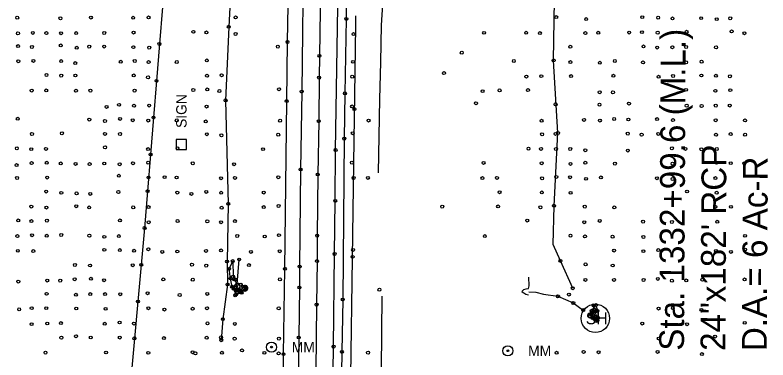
# Model space of a CAD drawing. Extents: x 20503438 to 20508873, y 7964251 to 7984667.
# Drawn here: x 20506371 to 20506880, y 7966054 to 7966287 of the extents above; entities that cross this region are included whole.
import ezdxf

# ---------------------------------------------------------------- set-up
doc = ezdxf.new("R2010")
doc.units = 0
for name, color, linetype in [('SurBreakLine', 7, 'Continuous'), ('SurDrainageArrowDown', 7, 'Continuous'), ('SurDrainageArrowUp', 7, 'Continuous'), ('SurEdgeRoadPaved', 7, 'Continuous'), ('SurEdgeShoulderPaved', 7, 'Continuous'), ('SurGuardRailCable', 7, 'Continuous'), ('SurNaturalCells', 7, 'Continuous'), ('SurPointsNonDTM', 7, 'Continuous'), ('SurRoadPoints', 7, 'Continuous'), ('SurSurveyPoints', 7, 'Continuous'), ('SurTxtDrainage', 7, 'Continuous')]:
    doc.layers.add(name, color=color, linetype=linetype)

msp = doc.modelspace()

# ---------------------------------------------------------------- linework, layer by layer
at = {"layer": 'SurBreakLine'}
for points in [[(20506582.81, 7966724.92), (20506582.26, 7966677.31), (20506582.09, 7966663.27), (20506581.59, 7966615.11), (20506580.38, 7966502.13), (20506579.87, 7966469.3), (20506579.47, 7966429.21), (20506579.05, 7966404.24), (20506578.73, 7966381.34), (20506578.04, 7966321.61), (20506576.98, 7966259.67), (20506576.78, 7966244.96), (20506576.56, 7966215.41), (20506575.87, 7966179.43), (20506575.47, 7966138), (20506575.36, 7966120.77), (20506575.03, 7966091.32), (20506574.47, 7966046.48)], [(20506524.33, 7966099.4), (20506520.71, 7966098.29), (20506517.91, 7966103.33), (20506516.85, 7966109.08), (20506515.87, 7966115.5), (20506518.34, 7966120.79), (20506518.54, 7966110.27), (20506519.05, 7966108.49), (20506521.38, 7966105.16)], [(20506521.38, 7966105.16), (20506522.69, 7966121.79)], [(20506718.49, 7966097.81), (20506716.49, 7966098.25), (20506715.19, 7966099.04), (20506714.23, 7966099.69), (20506714.38, 7966100.67), (20506715.33, 7966101.57), (20506716.74, 7966102.04), (20506718.43, 7966102.3), (20506718.95, 7966104.15), (20506718.63, 7966109.88)]]:
    msp.add_lwpolyline(points, dxfattribs=at)
for points in [[(20506523.75, 7966102.32), (20506523.75, 7966099.6), (20506521.29, 7966099.88), (20506519.07, 7966102.09), (20506518.23, 7966103.41), (20506520.53, 7966104.04), (20506521.78, 7966101.72)], [(20506764.96, 7966080.6), (20506763.97, 7966080.14), (20506761.46, 7966082.36), (20506760.29, 7966084.46), (20506761.04, 7966087.19), (20506762.83, 7966088.28), (20506762.39, 7966090.86), (20506764.05, 7966090.99), (20506765.05, 7966087.15), (20506765.42, 7966082.37)], [(20506763.1, 7966081.62), (20506762.52, 7966082.44), (20506761.57, 7966084.28), (20506762.93, 7966086.64), (20506763.82, 7966086.68), (20506763.93, 7966083.3), (20506764.35, 7966081.47)]]:
    msp.add_lwpolyline(points, close=True, dxfattribs=at)
at = {"layer": 'SurDrainageArrowDown'}
for points in [[(20506616.88, 7966180.41), (20506617.4, 7966205.4), (20506617.92, 7966230.4), (20506618.45, 7966255.39), (20506618.97, 7966280.39), (20506620.54, 7966305.33), (20506622.35, 7966330.27), (20506622.07, 7966354.47), (20506621.79, 7966378.67), (20506621.52, 7966402.88), (20506621.24, 7966427.08), (20506620.96, 7966451.29), (20506620.68, 7966475.49), (20506621.28, 7966497.96), (20506622.23, 7966519.72), (20506623.18, 7966541.47), (20506623.65, 7966564.87), (20506623.65, 7966589.87), (20506623.79, 7966614.5), (20506624.24, 7966638.28), (20506624.7, 7966662.06), (20506625.16, 7966685.84), (20506625.61, 7966709.62), (20506625.94, 7966733.94)], [(20506523.75, 7966721.59), (20506524.08, 7966654.91), (20506523.46, 7966584.86), (20506526.32, 7966516.32), (20506520.79, 7966470.76), (20506521.88, 7966436.58), (20506518.64, 7966398.81), (20506514.26, 7966328.87), (20506517.2, 7966310.23), (20506515.68, 7966279.39), (20506513.5, 7966229.59), (20506515.33, 7966159.59), (20506514.55, 7966120.49), (20506514.84, 7966104.97), (20506511.67, 7966081.49), (20506510.59, 7966067.23)], [(20506470.8, 7966292.66), (20506468.79, 7966267.75), (20506466.78, 7966242.83), (20506464.76, 7966217.91), (20506462.75, 7966192.99), (20506460.74, 7966168.07), (20506458.72, 7966143.16), (20506456.48, 7966118.26), (20506454.18, 7966093.37), (20506451.89, 7966068.48), (20506449.59, 7966043.59)], [(20506619.2, 7966097.06), (20506618.97, 7966072.88), (20506618.74, 7966047.06), (20506618.49, 7966020.9), (20506618.27, 7965997.06), (20506618.04, 7965972.06), (20506617.81, 7965947.06), (20506617.58, 7965922.17), (20506617.16, 7965898.81), (20506616.37, 7965877.03), (20506615.69, 7965858.08), (20506614.95, 7965837.72), (20506614.27, 7965818.75), (20506613.48, 7965796.99), (20506612.75, 7965776.62), (20506612.14, 7965759.68)]]:
    msp.add_lwpolyline(points, dxfattribs=at)
at = {"layer": 'SurDrainageArrowUp'}
for points in [[(20506748.37, 7966102.43), (20506739.98, 7966120.94), (20506735.03, 7966132), (20506735.65, 7966158.21), (20506738.35, 7966207.5), (20506735.41, 7966256.62), (20506736, 7966297.52), (20506735.47, 7966344.97), (20506731.78, 7966371.15), (20506731.51, 7966393.42), (20506729.75, 7966442.32), (20506728.92, 7966490.67), (20506727.65, 7966541.52), (20506726.65, 7966586.02), (20506725.58, 7966633.07), (20506725.56, 7966682.41), (20506728.02, 7966733.71)], [(20506718.57, 7966099.98), (20506723.31, 7966099.83), (20506728.62, 7966098.37), (20506738.34, 7966096.95), (20506748.71, 7966092.43), (20506755.43, 7966087.63)]]:
    msp.add_lwpolyline(points, dxfattribs=at)
at = {"layer": 'SurEdgeRoadPaved'}
for points in [[(20506571.13, 7966726.82), (20506570.83, 7966695.86), (20506570.09, 7966639.42), (20506569.8, 7966614.3), (20506569.59, 7966591.6), (20506568.51, 7966495.95), (20506567.62, 7966430.5), (20506567.22, 7966396.52), (20506566.49, 7966355.87), (20506566.21, 7966336.33), (20506565, 7966235.53), (20506564.23, 7966182.81), (20506563.62, 7966117.05), (20506563.45, 7966102.98), (20506562.98, 7966069.12), (20506561.69, 7965956.65)], [(20506586.39, 7966046.04), (20506586.58, 7966062.88), (20506587.24, 7966125.61), (20506587.67, 7966161.5), (20506587.93, 7966195.96), (20506590.01, 7966334.68), (20506590.5, 7966371.48), (20506591.96, 7966478.18), (20506591.99, 7966480.99), (20506592.1, 7966489.42), (20506593.34, 7966593.17), (20506593.52, 7966612.66), (20506594.1, 7966668.59), (20506594.21, 7966677.21), (20506594.79, 7966724.61)]]:
    msp.add_lwpolyline(points, dxfattribs=at)
at = {"layer": 'SurEdgeShoulderPaved'}
for points in [[(20506552.57, 7966028.45), (20506552.68, 7966057.72), (20506553.65, 7966115.57), (20506554.86, 7966229.07), (20506555.39, 7966269.1), (20506555.74, 7966293.81), (20506557.36, 7966406.54), (20506557.74, 7966443.63), (20506558.13, 7966478.73), (20506558.55, 7966512.75), (20506558.65, 7966520.93), (20506559.14, 7966552.93), (20506559.31, 7966580.85), (20506559.62, 7966608.8), (20506561.22, 7966731.44)], [(20506600.27, 7966712.13), (20506599.16, 7966608.62), (20506599.01, 7966594.45), (20506598.05, 7966493.9), (20506597.53, 7966458.7), (20506596.92, 7966422.46), (20506595.16, 7966284.71), (20506594.2, 7966234.33), (20506593.75, 7966203.67), (20506592.8, 7966094.73), (20506592.19, 7966059.31), (20506591.79, 7966030.9)]]:
    msp.add_lwpolyline(points, dxfattribs=at)
at = {"layer": 'SurGuardRailCable'}
msp.add_lwpolyline([(20506596.16, 7965301.88), (20506594.34, 7965701.8), (20506594.71, 7965733.27), (20506595.45, 7965806.52), (20506596.03, 7965869.84), (20506597.23, 7965978.92), (20506600.18, 7966186.78), (20506601.51, 7966279.91), (20506601.63, 7966286.68)], dxfattribs=at)
at = {"layer": 'SurNaturalCells'}
msp.add_circle((20506763.65, 7966082.03), 9.59, dxfattribs=at)
at = {"layer": 'SurPointsNonDTM'}
for centre in [(20506600.69, 7966223.66), (20506599.46, 7966123.68), (20506617.55, 7966101.43)]:
    msp.add_circle(centre, 1, dxfattribs=at)
at = {"layer": 'SurRoadPoints'}
msp.add_lwpolyline([(20506487.04, 7966199.68), (20506487.04, 7966199.68), (20506487.04, 7966203.11), (20506480.18, 7966203.11), (20506480.18, 7966196.25), (20506487.04, 7966196.25), (20506487.04, 7966199.68)], dxfattribs=at)
for centre, radius in [((20506544.57, 7966062.54), 3.43), ((20506544.57, 7966062.54), 0.571), ((20506704.46, 7966060.09), 3.43), ((20506704.46, 7966060.09), 0.571)]:
    msp.add_circle(centre, radius, dxfattribs=at)
at = {"layer": 'SurSurveyPoints'}
for centre in [(20506372.58, 7966285.52), (20506401.8, 7966285.12), (20506422.43, 7966285.59), (20506451.02, 7966285.46), (20506461.43, 7966285.73), (20506520.33, 7966285.69), (20506595.16, 7966284.71), (20506737.14, 7966285.93), (20506757.4, 7966284.59), (20506795.33, 7966285.87), (20506806.12, 7966285.52), (20506815.81, 7966285.03), (20506835.2, 7966285.21), (20506845.74, 7966284.54), (20506854.84, 7966285.1), (20506515.68, 7966279.39), (20506373.11, 7966274.94), (20506383.13, 7966275.23), (20506392.28, 7966275.11), (20506402.23, 7966275.01), (20506412.44, 7966275.12), (20506431.42, 7966275.19), (20506451.25, 7966275.44), (20506491.71, 7966275.96), (20506500.53, 7966275.54), (20506520.28, 7966274.5), (20506600.03, 7966274.44), (20506688.38, 7966275.28), (20506716.83, 7966275.36), (20506726.1, 7966275.09), (20506756.87, 7966275.11), (20506765.57, 7966275.31), (20506786.5, 7966275.48), (20506795.11, 7966275.73), (20506805.79, 7966275.38), (20506825.35, 7966276.01), (20506855.8, 7966276.25), (20506864.46, 7966275), (20506373.19, 7966266.32), (20506402.05, 7966266.78), (20506468.79, 7966267.75), (20506555.39, 7966269.1), (20506382.49, 7966265.71), (20506412.84, 7966265.2), (20506421.31, 7966265.94), (20506431.4, 7966265.95), (20506451.12, 7966265.59), (20506461.87, 7966265.24), (20506548.86, 7966265.92), (20506673.27, 7966261.84), (20506746.68, 7966265.86), (20506796.2, 7966266.08), (20506805.44, 7966265.32), (20506815.71, 7966265.5), (20506825.02, 7966265.72), (20506845.25, 7966265.45), (20506383.52, 7966256.28), (20506402.3, 7966256.13), (20506452.11, 7966256.24), (20506500.83, 7966256.58), (20506576.98, 7966259.67), (20506708.48, 7966256.19), (20506735.41, 7966256.62), (20506776.79, 7966256.2), (20506373.33, 7966256.02), (20506411.8, 7966254.81), (20506442.6, 7966255.69), (20506461.48, 7966255.5), (20506480.48, 7966255.51), (20506599.75, 7966255.64), (20506746.73, 7966255.49), (20506766.65, 7966255), (20506795.86, 7966255.25), (20506825.02, 7966255.32), (20506835.49, 7966255.74), (20506392.4, 7966246.75), (20506402.36, 7966246.31), (20506411.93, 7966246.41), (20506451.41, 7966246.45), (20506500.97, 7966246.25), (20506510.84, 7966246.61), (20506661.23, 7966248.03), (20506727.08, 7966245.95), (20506747.2, 7966246.02), (20506775.83, 7966246.22), (20506816.2, 7966246.09), (20506835.32, 7966246.4), (20506845.19, 7966246.21), (20506461.07, 7966245.14), (20506466.78, 7966242.83), (20506576.78, 7966244.96), (20506599.2, 7966245.6), (20506716.95, 7966245.65), (20506806.37, 7966245.57), (20506854.6, 7966245.84), (20506382.38, 7966236.22), (20506392.19, 7966236.32), (20506412.34, 7966236.08), (20506422.08, 7966236.15), (20506451.94, 7966236.14), (20506491.68, 7966236.61), (20506501.09, 7966236.99), (20506509.38, 7966235.9), (20506549.67, 7966237.07), (20506687.31, 7966235.81), (20506698.81, 7966236.36), (20506718.05, 7966236.52), (20506825.03, 7966236.71), (20506844.8, 7966236.02), (20506854.89, 7966236.47), (20506565, 7966235.53), (20506594.2, 7966234.33), (20506766.56, 7966235.1), (20506775.53, 7966234.99), (20506441.44, 7966226.56), (20506451.58, 7966225.94), (20506461.84, 7966226.07), (20506513.5, 7966229.59), (20506554.86, 7966229.07), (20506682.89, 7966227.64), (20506736.68, 7966226.86), (20506766.43, 7966226.65), (20506786.37, 7966227.42), (20506825.4, 7966225.98), (20506835.52, 7966225.73), (20506845.04, 7966226.01), (20506854.55, 7966226.03), (20506433.05, 7966225.15), (20506500.64, 7966225.38), (20506599.1, 7966225.47), (20506372.94, 7966217.09), (20506421.35, 7966216.57), (20506431.94, 7966215.61), (20506442.16, 7966217.02), (20506450.7, 7966216.14), (20506461.22, 7966215.91), (20506464.76, 7966217.91), (20506480.52, 7966216.05), (20506550.36, 7966215.8), (20506576.56, 7966215.41), (20506610.24, 7966215.92), (20506727.24, 7966215.77), (20506755.97, 7966216.37), (20506766.73, 7966215.9), (20506776.35, 7966216.93), (20506786.01, 7966216.63), (20506805.35, 7966216.91), (20506816.12, 7966216.23), (20506845, 7966216.11), (20506864.86, 7966216.01), (20506500.14, 7966215.31), (20506382.55, 7966206.81), (20506402.81, 7966207.26), (20506431.93, 7966206.85), (20506442.13, 7966206.83), (20506500.84, 7966206.64), (20506510.69, 7966205.92), (20506549.12, 7966206.33), (20506599.56, 7966207.35), (20506727.59, 7966206.6), (20506736.65, 7966206.89), (20506738.35, 7966207.5), (20506785.55, 7966207.06), (20506794.93, 7966206.37), (20506806.2, 7966206.9), (20506845.23, 7966206.26), (20506855.15, 7966206.72), (20506864.93, 7966206.34), (20506593.75, 7966203.67), (20506372.33, 7966197.12), (20506382.04, 7966196.54), (20506392.02, 7966196.7), (20506431.97, 7966197.8), (20506461.1, 7966196.58), (20506480.99, 7966197.16), (20506538.88, 7966196.53), (20506587.93, 7966195.96), (20506718.4, 7966196.87), (20506726.87, 7966196.7), (20506737.02, 7966196.67), (20506746.66, 7966196.66), (20506756.83, 7966195.8), (20506785.58, 7966195.6), (20506815.4, 7966197.11), (20506824.52, 7966196.74), (20506835.36, 7966196.44), (20506845.8, 7966196.63), (20506462.75, 7966192.99), (20506372.12, 7966185.73), (20506382.34, 7966187.08), (20506392.59, 7966187.31), (20506402.02, 7966186.9), (20506412.05, 7966186.56), (20506421.56, 7966186.44), (20506431.43, 7966186.84), (20506441.88, 7966186.33), (20506450.89, 7966186.99), (20506461.16, 7966187.39), (20506491.31, 7966186.97), (20506519.3, 7966186.36), (20506598.95, 7966187.41), (20506688.03, 7966187.22), (20506727.31, 7966187.02), (20506746.8, 7966186.56), (20506756.83, 7966187.33), (20506776.86, 7966186.75), (20506815.83, 7966186.72), (20506845.66, 7966187.43), (20506855.2, 7966187.06), (20506864.4, 7966187), (20506564.23, 7966182.81), (20506372.53, 7966177.04), (20506392.85, 7966177.3), (20506441.31, 7966178.51), (20506461.39, 7966177.3), (20506472.22, 7966177.59), (20506480.39, 7966177.36), (20506510.51, 7966176.87), (20506519.87, 7966177.08), (20506549.18, 7966177.52), (20506575.87, 7966179.43), (20506600.09, 7966177.03), (20506609.77, 7966177.12), (20506687.26, 7966176.93), (20506697.09, 7966177.08), (20506727.61, 7966176.81), (20506737.21, 7966177.78), (20506746.57, 7966177.54), (20506757.38, 7966176.47), (20506767.35, 7966177.43), (20506805.24, 7966176.83), (20506815.84, 7966176.36), (20506844.85, 7966176.93), (20506392.16, 7966167.84), (20506402.39, 7966167), (20506412.7, 7966166.62), (20506421.98, 7966166.25), (20506440.98, 7966167.54), (20506460.74, 7966168.07), (20506480.88, 7966167.13), (20506490.39, 7966166.29), (20506500.45, 7966167.63), (20506510.53, 7966167.03), (20506539.31, 7966167.19), (20506698.81, 7966167.36), (20506727.41, 7966167.29), (20506746.87, 7966167), (20506825.7, 7966167.9), (20506845.7, 7966167.02), (20506515.33, 7966159.59), (20506587.67, 7966161.5), (20506382.1, 7966157.68), (20506392.31, 7966157), (20506412.52, 7966157.88), (20506421.26, 7966157.12), (20506451.03, 7966157.17), (20506461.45, 7966157.36), (20506510.87, 7966156.91), (20506539.35, 7966157.36), (20506549.33, 7966158.1), (20506660.03, 7966157.63), (20506697.85, 7966157.77), (20506726.48, 7966157.18), (20506735.65, 7966158.21), (20506756.43, 7966157.65), (20506776.44, 7966157.1), (20506844.8, 7966157.59), (20506855.31, 7966157.51), (20506373.29, 7966148.28), (20506382.22, 7966147.88), (20506392.68, 7966148.15), (20506442.03, 7966148.33), (20506461.51, 7966147.05), (20506481.05, 7966147.91), (20506501.16, 7966147.72), (20506510.47, 7966147.11), (20506519.81, 7966147.89), (20506717.58, 7966148.2), (20506756.11, 7966147.06), (20506766.61, 7966147.97), (20506795.91, 7966147.49), (20506815.41, 7966147.25), (20506846.05, 7966147.4), (20506458.72, 7966143.16), (20506372.68, 7966137.72), (20506382.63, 7966138.28), (20506392.55, 7966137.95), (20506402.33, 7966138.47), (20506421.37, 7966137.99), (20506431.48, 7966137.19), (20506441.31, 7966137.7), (20506521.39, 7966137.78), (20506539.99, 7966137.43), (20506549.62, 7966138.34), (20506575.47, 7966138), (20506688.87, 7966137.72), (20506746.8, 7966137.97), (20506756.6, 7966137.47), (20506775.26, 7966137.31), (20506796.16, 7966137.12), (20506864.9, 7966137.89), (20506461.29, 7966128.78), (20506372.99, 7966127.74), (20506383.46, 7966127.52), (20506431.49, 7966128.41), (20506441.98, 7966128.23), (20506451.62, 7966127.79), (20506470.67, 7966127.02), (20506480.87, 7966127.27), (20506500.29, 7966127.66), (20506510.48, 7966128), (20506530.65, 7966127.02), (20506550.14, 7966127.45), (20506587.24, 7966125.61), (20506599.79, 7966128.33), (20506776.28, 7966127.91), (20506796.12, 7966127.5), (20506806.21, 7966128.26), (20506845.19, 7966127.73), (20506855.33, 7966126.98), (20506864.94, 7966128.64), (20506514.55, 7966120.49), (20506518.34, 7966120.79), (20506522.69, 7966121.79), (20506575.36, 7966120.77), (20506739.98, 7966120.94), (20506756.99, 7966118.58), (20506411.59, 7966118.14), (20506421.83, 7966117.81), (20506450.71, 7966117.97), (20506456.48, 7966118.26), (20506490.77, 7966118.39), (20506500.46, 7966117.7), (20506515.87, 7966115.5), (20506529.27, 7966118.07), (20506553.65, 7966115.57), (20506563.62, 7966117.05), (20506775.35, 7966117.79), (20506411.44, 7966108.48), (20506422.41, 7966108.8), (20506471.41, 7966108.38), (20506516.85, 7966109.08), (20506518.54, 7966110.27), (20506519.05, 7966108.49), (20506520.16, 7966108.4), (20506550.27, 7966108.42), (20506805.89, 7966108.71), (20506864.57, 7966108.39), (20506373.32, 7966106.92), (20506392.92, 7966107.59), (20506401.69, 7966107.55), (20506431.31, 7966107.8), (20506491.33, 7966108.19), (20506514.84, 7966104.97), (20506517.91, 7966103.33), (20506518.23, 7966103.41), (20506520.53, 7966104.04), (20506521.38, 7966105.16), (20506523.73, 7966104.9), (20506523.76, 7966104.63), (20506526.28, 7966103.6), (20506526.94, 7966103.51), (20506756.9, 7966108.03), (20506776.24, 7966108.04), (20506796.26, 7966108.01), (20506815.41, 7966107.51), (20506825.09, 7966107.72), (20506835.99, 7966108.12), (20506392.47, 7966098.63), (20506421.99, 7966098.43), (20506432.01, 7966098.45), (20506442.28, 7966098.36), (20506460.75, 7966099.06), (20506501.09, 7966098.56), (20506519.07, 7966102.09), (20506520.71, 7966098.29), (20506521.29, 7966099.88), (20506521.78, 7966101.72), (20506523.75, 7966102.32), (20506523.75, 7966099.6), (20506523.78, 7966100.74), (20506523.79, 7966100.42), (20506524.33, 7966099.4), (20506526.53, 7966101.21), (20506526.82, 7966101.53), (20506527.18, 7966102.93), (20506527.19, 7966101.64), (20506527.31, 7966102.2), (20506527.37, 7966102.91), (20506527.41, 7966102.09), (20506563.45, 7966102.98), (20506748.37, 7966102.43), (20506412.29, 7966098.01), (20506454.18, 7966093.37), (20506482.48, 7966097.82), (20506520.01, 7966097.63), (20506592.8, 7966094.73), (20506738.34, 7966096.95), (20506745.73, 7966098.13), (20506373.89, 7966088.11), (20506382.36, 7966088.91), (20506392.19, 7966088.93), (20506412.53, 7966088.71), (20506432.35, 7966088.48), (20506461.31, 7966088.89), (20506491.23, 7966088.55), (20506500.96, 7966088.85), (20506549.45, 7966088.79), (20506575.03, 7966091.32), (20506748.71, 7966092.43), (20506762.39, 7966090.86), (20506762.83, 7966088.28), (20506764.05, 7966090.99), (20506806.39, 7966088.68), (20506816.04, 7966089.02), (20506472.13, 7966087.99), (20506755.43, 7966087.63), (20506760.29, 7966084.46), (20506761.04, 7966087.19), (20506761.57, 7966084.28), (20506762.93, 7966086.64), (20506763.82, 7966086.68), (20506763.93, 7966083.3), (20506765.05, 7966087.15), (20506835.39, 7966087.75), (20506382.32, 7966078.1), (20506392.88, 7966078.56), (20506402.14, 7966078.82), (20506431.77, 7966078.36), (20506441.81, 7966079.23), (20506451.55, 7966078.51), (20506501.27, 7966078.64), (20506511.67, 7966081.49), (20506519.78, 7966078.3), (20506761.46, 7966082.36), (20506762.52, 7966082.44), (20506763.1, 7966081.62), (20506763.97, 7966080.14), (20506764.35, 7966081.47), (20506764.96, 7966080.6), (20506765.42, 7966082.37), (20506795.34, 7966078.48), (20506825.69, 7966078.04), (20506864.7, 7966079.01), (20506402.44, 7966068.96), (20506412.36, 7966069.89), (20506422.32, 7966069.06), (20506441.91, 7966068.99), (20506451.89, 7966068.48), (20506471.8, 7966068.69), (20506500.73, 7966068.87), (20506510.46, 7966069.16), (20506519.63, 7966068.3), (20506549.61, 7966068.3), (20506562.98, 7966069.12), (20506806.51, 7966068.33), (20506844.64, 7966069.69), (20506510.59, 7966067.23), (20506586.58, 7966062.88), (20506391.7, 7966058.81), (20506432.68, 7966058.92), (20506461.24, 7966058.7), (20506491.22, 7966059.07), (20506493.06, 7966058.37), (20506511.01, 7966058.73), (20506524.63, 7966060.31), (20506539.79, 7966058.7), (20506549.42, 7966058.28), (20506552.68, 7966057.72), (20506592.19, 7966059.31), (20506609.87, 7966058.83), (20506737.37, 7966058.75), (20506755.7, 7966059.3), (20506765.77, 7966059.1), (20506805.73, 7966059.33), (20506835.71, 7966057.82)]:
    msp.add_circle(centre, 1, dxfattribs=at)

# ---------------------------------------------------------------- texts
at = {"layer": 'SurNaturalCells'}
msp.add_text('SH', height=7.995, rotation=360, dxfattribs=at).set_placement((20506757.13, 7966078.03))
at = {"layer": 'SurRoadPoints'}
for s, rotation, p in [('SIGN', 89.9987, (20506487.11, 7966210.89)), ('MM', 360, (20506558.28, 7966059.04)), ('MM', 360, (20506718.17, 7966056.59))]:
    msp.add_text(s, height=6.995, rotation=rotation, dxfattribs=at).set_placement(p)
at = {"layer": 'SurTxtDrainage'}
for s, p in [('Sta. 1332+99.6 (M.L.)', (20506823.55, 7966060.08)), ('24"x182\' RCP', (20506851.55, 7966059.93)), ('D.A.= 6 Ac-R', (20506879.55, 7966059.78))]:
    msp.add_text(s, height=16.8, rotation=89.6917, dxfattribs=at).set_placement(p)

doc.saveas('drawing.dxf')
